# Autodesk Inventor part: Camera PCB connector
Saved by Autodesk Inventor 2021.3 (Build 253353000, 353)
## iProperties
Created: 2023-02
Part Number: Camera PCB connector
Material: Generic
Document SubType Name: Modeling
Designer: AdminForWorker
Density: 1 g/cm^3
Appearance: Default
Title: Camera PCB connector
Author: AdminForWorker
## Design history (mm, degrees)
feature "Body1"
body "Solid1"
